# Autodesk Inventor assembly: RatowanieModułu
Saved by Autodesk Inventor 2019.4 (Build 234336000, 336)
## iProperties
Created: 2020-01
Part Number: RatowanieModułu
Document SubType Name: Assembly
Designer: Administrator
Title: RatowanieModułu v3
Author: Administrator
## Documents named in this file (3)
- c:\worker\convert-fusion-r01\tmp\job-1\36\output\files\9be13dbb-4289-4c70-bb27-03d32c1206a2\6577c852-da78-4e69-8fde-6e8a249befa6.iam
- c:\worker\convert-fusion-r01\tmp\job-1\36\output\files\9be13dbb-4289-4c70-bb27-03d32c1206a2\Rama v7.iam
- c:\worker\convert-fusion-r01\tmp\job-1\36\output\files\9be13dbb-4289-4c70-bb27-03d32c1206a2\Mocowanie v6.ipt
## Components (2 placed, 2 different names)
1. Rama v7:1 [sub-assembly]
2. Mocowanie v6:1
